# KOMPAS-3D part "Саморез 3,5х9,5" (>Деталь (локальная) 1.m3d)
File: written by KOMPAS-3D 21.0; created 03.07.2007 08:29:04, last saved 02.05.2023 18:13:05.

Document properties: Полное имя файла: C:\Users\Константин Сергеев\AppData\Local\Temp\KOMPAS-3D\ktfa-1813-153c-7cb1\_Деталь (локальная) 1.m3d

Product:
- Part/product: Саморез 3,5х9,5
    Масса: 0.001484

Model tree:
1. Плоскость XY
2. Плоскость ZX
3. Плоскость ZY
4. Ось X
5. Ось Y
6. Ось Z
7. Начало координат
8. Эскиз:1
9. Операция вращения:1
     Угол 1 = 360
10. Эскиз:2
11. Смещенная плоскость:1
     Расстояние = 2
12. Эскиз:4
13. Вырезать элемент по сечениям:1  (labels: Коэффициент 1; Коэффициент 2)
     Толщина стенки 1 = 1; Толщина стенки 2 = 1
